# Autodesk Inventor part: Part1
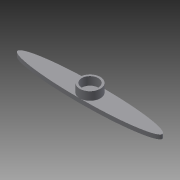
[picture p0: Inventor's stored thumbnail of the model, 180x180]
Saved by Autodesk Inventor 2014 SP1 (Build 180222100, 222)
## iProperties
Created: 2017-05
Part Number: Part1
Material: Generic
Document SubType Name: Modeling
Designer: L.Đ.P
Density: 1 g/cm^3
Appearance: Default
Author: L.Đ.P
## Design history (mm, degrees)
sketch "Sketch1" dims "d0" = 17.5
  geometry: L1 (0, 0)-(0, -2.5); 1 further point; 1 other entity
  constraints: 2 end point, 1 coincident, 1 vertical, 1 vertical alignment, 2 other
  dimensions: "d1" = 2.5 distance of L1.start L1.end
extrude "Extrusion1" new body sketch "Sketch1" stored distance "d2" = 1; taper "d3" = 0 deg
sketch "Sketch2"
  geometry: C1 r 3 at (0, 0); 1 further point; 1 other entity
  constraints: 1 centre point, 1 coincident, 1 other
  dimensions: "d4" = 6 diameter of C1
extrude "Extrusion2" join sketch "Sketch2" distance "d5" = 2; taper "d6" = 0 deg; dims "d23" = 1, "d24" = 0
sketch "Sketch3"
  geometry: C1 r 3 at (0, 0) reference; C2 r 2.5 at (0, 0)
  constraints: 1 centre point, 1 coincident
  dimensions: "d7" = 5 diameter of C2
extrude "Extrusion3" cut sketch "Sketch3" distance "d8" = 2; taper "d9" = 0 deg
sketch "Sketch4"
  geometry: C1 r 2 at (0, 0); 1 further point; 1 other entity
  constraints: 1 centre point, 1 coincident, 1 other
  dimensions: "d10" = 4 diameter of C1
extrude "Extrusion4" cut sketch "Sketch4" distance "d11" = 0.5; taper "d12" = 0 deg
sketch "Sketch5"
  geometry: C1 r 2 at (0, 0) reference; C2 r 1 at (0, 0)
  constraints: 1 centre point, 1 coincident
  dimensions: "d13" = 2 diameter of C2
extrude "Extrusion5" cut sketch "Sketch5" stored distance "d14" = 1; taper "d15" = 0 deg
sketch "Sketch6"
  geometry: L1 (0, 0)-(0, -1.269); L2 (0, 0)-(-1.481, 0); C1 r 0.5 at (-16, 0); 1 other entity
  constraints: 4 end point, 1 centre point, 1 perpendicular, 1 point on line, 1 vertical, 1 other
  dimensions: "d16" = 1 diameter of C1; "d17" = 16 distance of L1.start C1.centre
extrude "Extrusion6" cut sketch "Sketch6" stored distance "d18" = 1; taper "d19" = 0 deg
pattern_linear "Rectangular Pattern1" dims "d22" = 2.5
mirror "Mirror2"
body "Solid1"
